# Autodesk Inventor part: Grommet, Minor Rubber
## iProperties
Title: Grommet, Minor Rubber
Author: halg
Created: 2002-04
Part Number: Minor Grommet
Material: Silicone Rubber
Description: Grommet, .125 in ID, .3125 in OD, .1875 in Thk
Document SubType Name: Modeling
Designer: halg
Control State: 0
Master: False
Checked Out: False
Last Check In By: halg
Last Check In Date: 2002-05-03
PropertySet Name: Design Tracking Control
Shininess: 20.0
Length Units: 11272
Angle Units: 11286
Time Units: 11279
Mass Units: 11290
Length Display Precision: 3
Angle Display Precision: 2
Compacted: True
PropertySet Name: _Private Model Information
Density: 1.25
Volumn: 0.14124053343716367
Area: 2.793477168989194
PropertySet Name: Model Information
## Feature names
1. Revolution1
2. Fillet1
